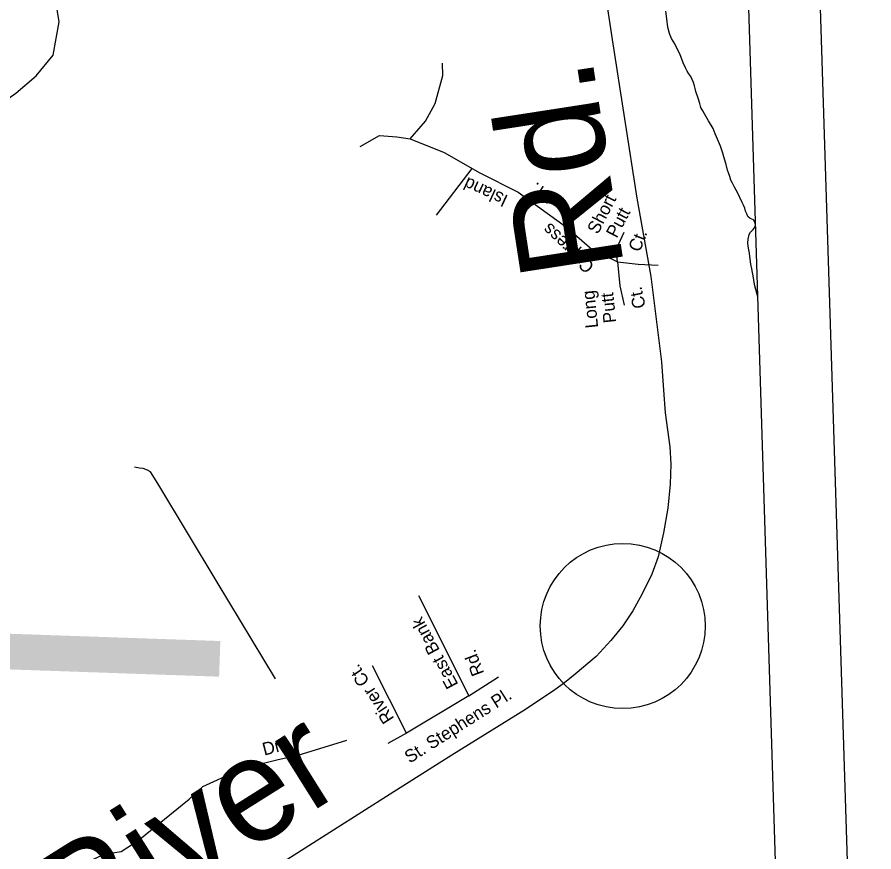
# Model space of a CAD drawing. Extents: x 2308163 to 2335412, y -96774 to 127732.
# Drawn here: x 2326403.9 to 2326493.2, y 123011.9 to 123098.9 of the extents above; entities that cross this region are included whole.
import ezdxf

# ---------------------------------------------------------------- set-up
doc = ezdxf.new("R2010")
doc.units = 0
for name, color, linetype in [('Default', 7, 'Continuous'), ('Old_Level_1', 7, 'Continuous'), ('Old_Level_10', 7, 'Continuous'), ('Old_Level_11', 7, 'Continuous'), ('Old_Level_22', 7, 'Continuous'), ('Old_Level_32', 7, 'Continuous'), ('Old_Level_35', 7, 'Continuous'), ('Old_Level_60', 7, 'Continuous')]:
    doc.layers.add(name, color=color, linetype=linetype)

msp = doc.modelspace()

# ---------------------------------------------------------------- linework, layer by layer
at = {"layer": 'Default'}
msp.add_circle((2326467.048, 123035.444), 8.606, dxfattribs=at)
at = {"layer": 'Old_Level_1'}
for p, q in [((2326493.248, 122923.687), (2326476.609, 123451.753)), ((2326485.516, 122930.947), (2326469.349, 123444.02))]:
    msp.add_line(p, q, dxfattribs=at)
at = {"layer": 'Old_Level_32'}
msp.add_lwpolyline([(2326464.59, 123105.565), (2326465.946, 123096.627), (2326468.532, 123080.073), (2326469.972, 123071.877), (2326470.737, 123065.77), (2326471.084, 123062.998), (2326471.291, 123060.035), (2326471.483, 123057.688), (2326471.95, 123054.139), (2326472.064, 123052.326), (2326471.992, 123050.237), (2326471.764, 123047.727), (2326471.285, 123045.155), (2326470.738, 123042.656), (2326470.072, 123040.836), (2326469.08, 123038.813), (2326468.096, 123037.039), (2326467.048, 123035.444), (2326465.789, 123033.927), (2326464.278, 123032.277), (2326462.085, 123030.403), (2326460.955, 123029.52), (2326459.961, 123028.792), (2326456.907, 123026.745), (2326449.229, 123021.977), (2326442.794, 123017.902), (2326430.969, 123010.413)], dxfattribs=at)
at = {"layer": 'Old_Level_35'}
for points in [[(2326367.517, 123068.14), (2326400.847, 123088.994), (2326403.727, 123091.022), (2326405.832, 123092.821), (2326407.609, 123094.972), (2326408.24, 123098.439), (2326407.75, 123101.519)], [(2326444.854, 123086.238), (2326446.47, 123088.078), (2326447.483, 123089.94), (2326448.273, 123092.843), (2326448.231, 123094.138)], [(2326439.652, 123085.469), (2326441.675, 123086.606), (2326443.481, 123086.457), (2326444.854, 123086.238), (2326448.428, 123084.821), (2326452.15, 123082.711), (2326456.134, 123080.677), (2326461.185, 123077.055), (2326463.865, 123074.721), (2326466.494, 123073.424), (2326466.366, 123074.721), (2326467.204, 123076.502)], [(2326447.599, 123078.299), (2326451.341, 123083.17)], [(2326466.494, 123073.424), (2326466.752, 123070.915), (2326467.201, 123068.917)], [(2326466.494, 123073.424), (2326468.642, 123073.177), (2326470.736, 123073.089)], [(2326430.8, 123029.949), (2326424.741, 123040.012), (2326418.528, 123050.32), (2326417.782, 123051.522), (2326417.462, 123051.687), (2326417.021, 123051.858), (2326416.615, 123051.909), (2326416.088, 123052.006)], [(2326445.747, 123038.609), (2326450.994, 123028.17), (2326454.08, 123030.133)], [(2326444.476, 123024.258), (2326440.922, 123031.276)], [(2326450.994, 123028.17), (2326444.476, 123024.258), (2326442.542, 123023.204)], [(2326389.796, 123003.474), (2326397.713, 123004.925), (2326400.838, 123005.506), (2326405.508, 123005.863), (2326407.802, 123007.335), (2326409.578, 123008.825), (2326411.2, 123010.838), (2326412.988, 123011.638), (2326414.723, 123011.923), (2326416.487, 123013.069), (2326421.811, 123017.368), (2326423.237, 123018.698), (2326427.444, 123020.622), (2326431.098, 123021.53), (2326433.183, 123021.975), (2326438.24, 123023.525)]]:
    msp.add_lwpolyline(points, dxfattribs=at)
at = {"layer": 'Old_Level_60'}
for points in [[(2326472.145, 123096.732), (2326471.921, 123097.238), (2326471.793, 123097.755), (2326471.708, 123098.144), (2326471.665, 123098.476), (2326471.554, 123099.557)], [(2326480.261, 123074.329), (2326480.191, 123074.677), (2326480.128, 123075.065), (2326480.093, 123075.417), (2326480.124, 123075.787), (2326480.224, 123076.266), (2326480.362, 123076.505), (2326480.669, 123076.809), (2326480.861, 123077.062), (2326480.898, 123077.315), (2326480.83, 123077.561), (2326480.673, 123077.79), (2326480.331, 123077.959), (2326480.104, 123078.15), (2326479.989, 123078.413), (2326479.871, 123078.717), (2326479.772, 123079.03), (2326479.633, 123079.34), (2326479.5, 123079.614), (2326479.262, 123080.145), (2326479.109, 123080.43), (2326478.872, 123080.911), (2326478.712, 123081.211), (2326478.482, 123081.615), (2326478.326, 123081.926), (2326478.209, 123082.306), (2326478.072, 123082.707), (2326477.989, 123082.999), (2326477.836, 123083.589), (2326477.589, 123084.385), (2326477.479, 123084.77), (2326477.344, 123085.161), (2326477.243, 123085.484), (2326476.816, 123086.464), (2326476.688, 123086.769), (2326476.467, 123087.325), (2326475.991, 123088.129), (2326475.587, 123088.859), (2326475.397, 123089.181), (2326475.204, 123089.533), (2326475.083, 123089.929), (2326474.964, 123090.4), (2326474.683, 123091.177), (2326474.599, 123091.485), (2326474.536, 123091.792), (2326474.444, 123092.125), (2326474.306, 123092.43), (2326474.14, 123092.746), (2326473.951, 123093.032), (2326473.778, 123093.317), (2326473.596, 123093.648), (2326473.356, 123094.185), (2326472.986, 123095.107), (2326472.734, 123095.65), (2326472.475, 123096.162), (2326472.145, 123096.732)], [(2326481.146, 123069.771), (2326481.023, 123070.161), (2326480.812, 123070.91), (2326480.749, 123071.289), (2326480.658, 123071.947), (2326480.591, 123072.3), (2326480.503, 123072.705), (2326480.42, 123073.175), (2326480.318, 123073.991), (2326480.261, 123074.329)]]:
    msp.add_lwpolyline(points, dxfattribs=at)

# ---------------------------------------------------------------- texts
at = {"layer": 'Old_Level_10'}
for s, height, rotation, p in [(' Island ', 1.3328, 155.20343, (2326455.625, 123080.092)), ('Dr.', 1.3328, 146.86381, (2326459.998, 123080.5)), ('Short', 1.3328, 62.50556, (2326464.445, 123076.221)), ('Putt', 1.3328, 62.50556, (2326466.414, 123075.82)), ('Cypress', 1.3328, 136.19916, (2326464.166, 123073.053)), ('Ct.', 1.3328, 68.66812, (2326468.82, 123074.361)), ('Long', 1.3328, 95.97678, (2326464.489, 123066.567)), ('Ct.', 1.3328, 101.76918, (2326469.452, 123068.698)), ('Putt', 1.3328, 95.97678, (2326466.376, 123067.107)), ('East Bank', 1.3328, 118.32588, (2326449.924, 123029.348)), ('Rd.', 1.3328, 110.76451, (2326452.611, 123030.53)), ('River Ct.', 1.3328, 123.40587, (2326443.242, 123025.798)), ('St. Stephens Pl.', 1.33284, 32.47615, (2326444.814, 123021.076)), ('Dr.', 1.3328, 14.48431, (2326429.639, 123021.92))]:
    msp.add_text(s, height=height, rotation=rotation, dxfattribs=at).set_placement(p)
at = {"layer": 'Old_Level_11'}
for s, rotation, p in [('Rd.', 98.78086, (2326467.225, 123072.804)), ('River', 32.15379, (2326409.92, 123000.521))]:
    msp.add_text(s, height=10.796, rotation=rotation, dxfattribs=at).set_placement(p)
at = {"layer": 'Old_Level_22'}
msp.add_text('T', height=29.989, rotation=88.02472, dxfattribs=at).set_placement((2326424.572, 123019.787))

doc.saveas('drawing.dxf')
